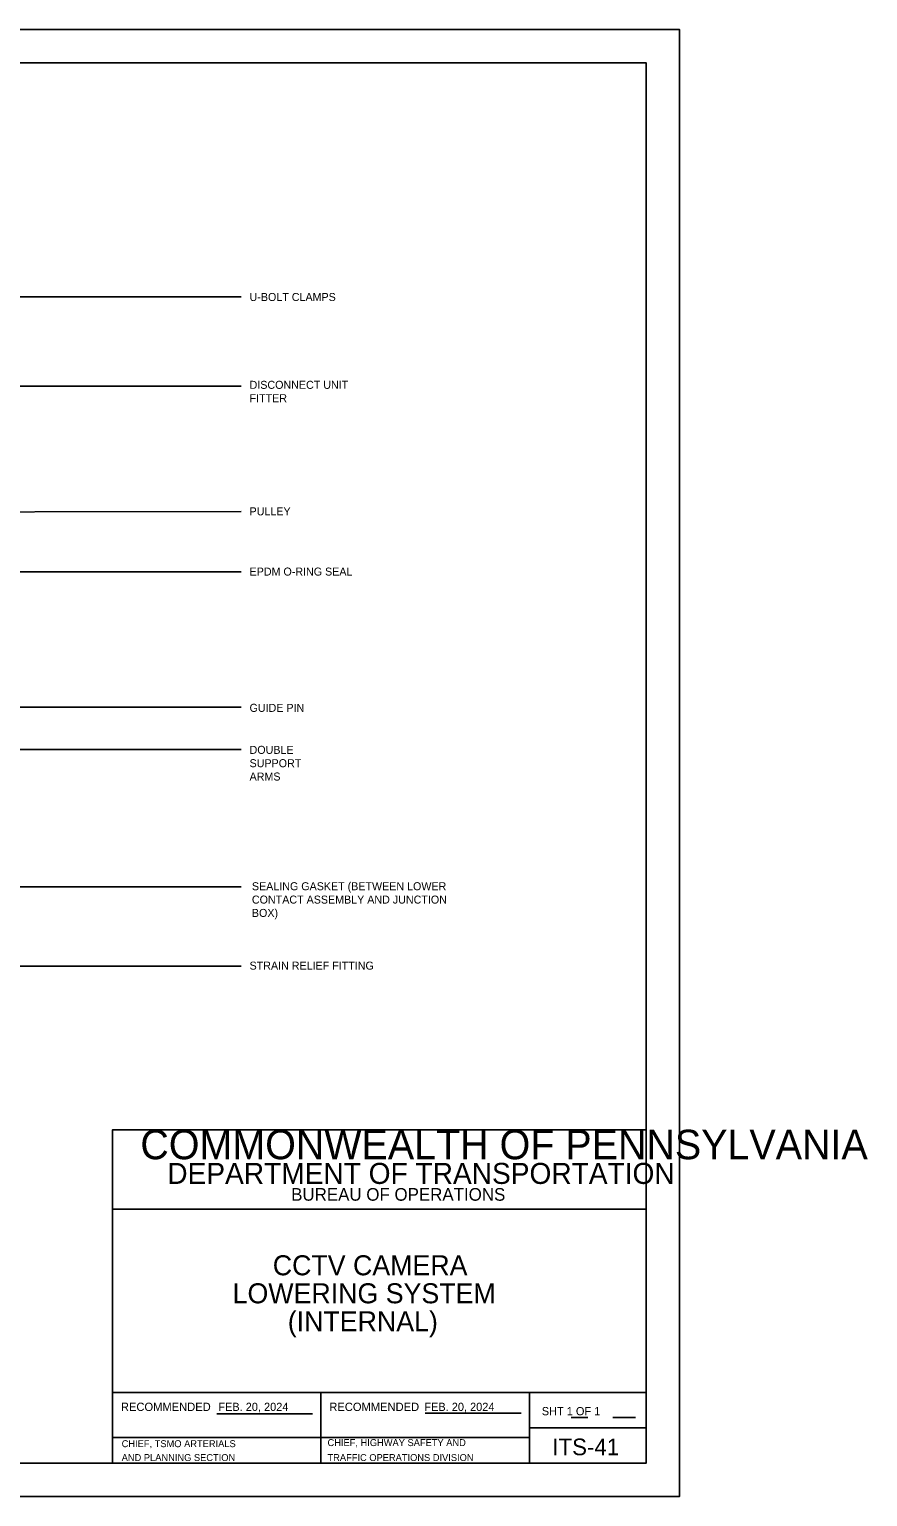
# Model space of a CAD drawing. Extents: x 1299104.6 to 1299141.4, y 239713.3 to 239735.3.
# Drawn here: x 1299128.87 to 1299141.45, y 239713.27 to 239735.27 of the extents above; entities that cross this region are included whole.
import ezdxf

# ---------------------------------------------------------------- set-up
doc = ezdxf.new("R2010")
doc.units = 0
for name, color, linetype in [('1', 7, 'Continuous'), ('2', 7, 'Continuous'), ('DIM TXT', 7, 'Continuous'), ('GS_plotshape_p', 7, 'Continuous'), ('Level 1', 7, 'Continuous'), ('Level 8', 7, 'Continuous'), ('PTEXT', 7, 'Continuous')]:
    doc.layers.add(name, color=color, linetype=linetype)

msp = doc.modelspace()

# ---------------------------------------------------------------- linework, layer by layer
at = {"layer": '1'}
for p, q in [((1299131.685, 239714.516), (1299133.122, 239714.516)), ((1299134.81, 239714.525), (1299136.247, 239714.525)), ((1299130.122, 239714.161), (1299133.247, 239714.161))]:
    msp.add_line(p, q, dxfattribs=at)
at = {"layer": 'GS_plotshape_p'}
msp.add_lwpolyline([(1299104.622, 239735.273), (1299138.622, 239735.273), (1299138.622, 239713.273), (1299104.622, 239713.273)], close=True, dxfattribs=at)
at = {"layer": 'Level 1'}
for p, q in [((1299130.122, 239714.835), (1299138.122, 239714.835)), ((1299133.247, 239713.773), (1299133.247, 239714.835)), ((1299136.372, 239713.773), (1299136.372, 239714.835)), ((1299136.997, 239714.46), (1299137.247, 239714.46)), ((1299137.622, 239714.46), (1299137.966, 239714.46)), ((1299136.372, 239714.304), (1299138.122, 239714.304)), ((1299133.247, 239714.161), (1299136.372, 239714.161))]:
    msp.add_line(p, q, dxfattribs=at)
for points in [[(1299138.122, 239713.773), (1299106.122, 239713.773), (1299106.122, 239734.773), (1299138.122, 239734.773)], [(1299130.122, 239713.773), (1299138.122, 239713.773), (1299138.122, 239718.773), (1299130.122, 239718.773)], [(1299130.122, 239718.773), (1299138.122, 239718.773), (1299138.122, 239717.585), (1299130.122, 239717.585)]]:
    msp.add_lwpolyline(points, close=True, dxfattribs=at)
at = {"layer": 'Level 8'}
for points in [[(1299123.113, 239728.677), (1299123.113, 239728.677), (1299126.285, 239731.263), (1299132.012, 239731.263)], [(1299123.904, 239728.712), (1299126.285, 239731.263), (1299132.049, 239731.263)], [(1299124.939, 239728.458), (1299125.607, 239729.925), (1299132.049, 239729.925)], [(1299125.034, 239727.806), (1299125.85, 239728.033), (1299132.049, 239728.042)], [(1299125.805, 239727.053), (1299128.037, 239727.138), (1299132.049, 239727.138)], [(1299125.129, 239725.488), (1299126.094, 239725.108), (1299132.049, 239725.108)], [(1299125.271, 239724.857), (1299126.236, 239724.477), (1299132.049, 239724.477)], [(1299125.678, 239723.466), (1299128.303, 239722.417), (1299132.049, 239722.417)], [(1299124.999, 239722.731), (1299126.64, 239721.228), (1299132.049, 239721.228)]]:
    msp.add_lwpolyline(points, dxfattribs=at)

# ---------------------------------------------------------------- texts
at = {"layer": '1'}
for s, height, p in [('COMMONWEALTH OF PENNSYLVANIA', 0.44223, (1299130.538, 239718.332)), ('DEPARTMENT OF TRANSPORTATION', 0.31514, (1299130.942, 239717.962)), ('BUREAU OF OPERATIONS', 0.18955, (1299132.8, 239717.71)), ('RECOMMENDED', 0.125, (1299130.247, 239714.557)), ('FEB. 20, 2024', 0.12303, (1299131.707, 239714.558)), ('RECOMMENDED', 0.125, (1299133.372, 239714.557)), ('FEB. 20, 2024', 0.12303, (1299134.797, 239714.558)), ('CHIEF, TSMO ARTERIALS ', 0.10417, (1299130.258, 239714.015)), ('CHIEF, HIGHWAY SAFETY AND ', 0.10417, (1299133.345, 239714.031)), ('AND PLANNING SECTION', 0.10417, (1299130.258, 239713.807)), ('TRAFFIC OPERATIONS DIVISION', 0.10417, (1299133.345, 239713.807))]:
    msp.add_text(s, height=height, dxfattribs=at).set_placement(p)
at = {"layer": '2'}
msp.add_text('SHT 1 OF 1', height=0.123, dxfattribs=at).set_placement((1299136.558, 239714.493))
at = {"layer": 'DIM TXT'}
for s, p in [('U-BOLT CLAMPS', (1299132.176, 239731.2)), ('DISCONNECT UNIT ', (1299132.176, 239729.883)), ('FITTER', (1299132.176, 239729.683)), ('PULLEY', (1299132.176, 239727.986)), ('EPDM O-RING SEAL', (1299132.176, 239727.083)), ('GUIDE PIN', (1299132.176, 239725.04)), ('SUPPORT', (1299132.176, 239724.21)), ('DOUBLE', (1299132.176, 239724.41)), ('ARMS', (1299132.176, 239724.01)), ('SEALING GASKET (BETWEEN LOWER ', (1299132.211, 239722.365)), ('CONTACT ASSEMBLY AND JUNCTION ', (1299132.211, 239722.165)), ('BOX)', (1299132.211, 239721.965)), ('STRAIN RELIEF FITTING', (1299132.176, 239721.175))]:
    msp.add_text(s, height=0.12, dxfattribs=at).set_placement(p)
at = {"layer": 'PTEXT'}
for s, height, p in [('CCTV CAMERA', 0.3, (1299132.524, 239716.592)), ('LOWERING SYSTEM', 0.3, (1299131.922, 239716.172)), ('(INTERNAL)', 0.3, (1299132.749, 239715.752)), ('ITS-41', 0.25, (1299136.716, 239713.894))]:
    msp.add_text(s, height=height, dxfattribs=at).set_placement(p)

doc.saveas('drawing.dxf')
